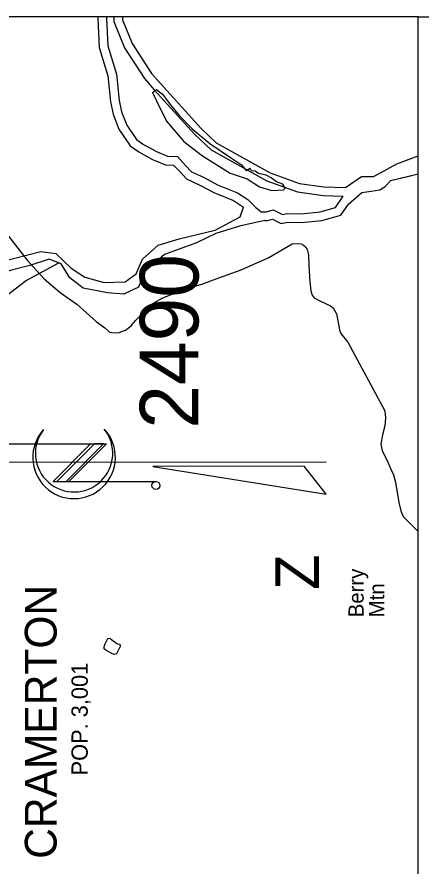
# Model space of a CAD drawing. Extents: x 1372027 to 1374286, y 553832 to 556743.
# Drawn here: x 1373419 to 1373483.1, y 554256.9 to 554391.5 of the extents above; entities that cross this region are included whole.
import ezdxf

# ---------------------------------------------------------------- set-up
doc = ezdxf.new("R2010")
doc.units = 0
for name, color, linetype in [('Old_Level_12', 7, 'Continuous'), ('Prop Dimension', 7, 'Continuous'), ('Prop Dimension Text', 7, 'Continuous'), ('Prop Lane Arrow CELL', 7, 'Continuous'), ('Prop Paved Shoulder', 7, 'Continuous'), ('Prop Terminator CELL', 7, 'Continuous'), ('Sheet Block Revision CELL', 7, 'Continuous'), ('Sheet Clip Boundary CELL', 7, 'Continuous'), ('Sheet North Arrow CELL', 7, 'Continuous'), ('Sheet Plot Border Outside CELL', 7, 'Continuous'), ('Sheet Sticker Incomplete CELL', 7, 'Continuous'), ('Sheet Sticker Preliminary CELL', 7, 'Continuous')]:
    doc.layers.add(name, color=color, linetype=linetype)

msp = doc.modelspace()

# ---------------------------------------------------------------- linework, layer by layer
at = {"layer": 'Prop Dimension'}
msp.add_lwpolyline([(1373425.61, 554352.52), (1373420.51, 554349.73), (1373415.69, 554346.11), (1373414.26, 554345.81), (1373409.04, 554343.48), (1373402.63, 554343.54), (1373401.31, 554342.34), (1373400.95, 554341.2), (1373387.17, 554323.46), (1373382.87, 554318.23)], dxfattribs=at)
at = {"layer": 'Prop Dimension Text'}
for points in [[(1373151.67, 554391.53), (1373151.67, 554060.53), (1373482.67, 554060.53), (1373482.67, 554391.53)], [(1373508.08, 554391.53), (1373508.08, 554060.53), (1373482.67, 554060.53), (1373482.67, 554391.53)]]:
    msp.add_lwpolyline(points, close=True, dxfattribs=at)
at = {"layer": 'Prop Lane Arrow CELL'}
for points in [[(1373440.5, 554379.56), (1373441.13, 554380.05), (1373442.12, 554379.28), (1373443.31, 554377.67), (1373444.79, 554375.84), (1373446.81, 554373.8), (1373449.62, 554371.48), (1373453.06, 554369.17), (1373454.61, 554368.11), (1373455.38, 554367.2), (1373456.01, 554367.55)], [(1373440.5, 554379.56), (1373441.12, 554378.23), (1373442.73, 554375), (1373445.47, 554371.77), (1373448.42, 554369.52), (1373452.85, 554366.78), (1373455.52, 554365.87), (1373457.49, 554364.6), (1373459.46, 554364.04), (1373461.28, 554364.11), (1373461.57, 554364.39), (1373461.21, 554365.02), (1373460.16, 554365.38), (1373459.32, 554366.01), (1373458.54, 554366.43), (1373457.35, 554366.71), (1373456.79, 554367.06), (1373456.22, 554367.13), (1373456.01, 554367.55)], [(1373399.91, 554348.56), (1373401.89, 554350.66), (1373405.48, 554350.79), (1373406.6, 554352.39), (1373412.17, 554351.4), (1373416.63, 554352.77), (1373422.82, 554354.37), (1373425.16, 554354.04), (1373427.61, 554351.7), (1373429.76, 554350.29), (1373432.86, 554349.42), (1373436.2, 554349.55), (1373437.94, 554350.79), (1373438.93, 554353.14), (1373441.4, 554355.37), (1373444.75, 554356.36), (1373450.45, 554357.72), (1373454.41, 554359.82), (1373454.97, 554361.36)], [(1373458.31, 554359.26), (1373454.29, 554358.34), (1373450.57, 554357.22), (1373447.47, 554355.74), (1373442.4, 554353.88), (1373439.3, 554351.16), (1373438.31, 554348.68), (1373435.95, 554347.57), (1373433.35, 554347.81), (1373429.51, 554348.56), (1373427.41, 554350.17), (1373426.04, 554352.39), (1373424.11, 554353.13), (1373421.03, 554352.12), (1373418.12, 554351.4), (1373415.27, 554350.54), (1373410.81, 554350.29), (1373406.35, 554351.03), (1373401.89, 554349.79), (1373400.28, 554348.31)]]:
    msp.add_lwpolyline(points, dxfattribs=at)
at = {"layer": 'Prop Paved Shoulder'}
msp.add_line((1373417.68, 554356.76), (1373420.64, 554352.96), dxfattribs=at)
msp.add_lwpolyline([(1373420.64, 554352.96), (1373423.32, 554350), (1373425.88, 554347.83), (1373427.28, 554346.83), (1373428.53, 554345.99), (1373431.55, 554343.24), (1373432.97, 554342.24), (1373433.65, 554341.62), (1373434.01, 554341.52), (1373434.74, 554341.46), (1373435.24, 554341.52), (1373436.22, 554341.9), (1373437.12, 554342.57), (1373437.83, 554343.42), (1373438.59, 554344.18), (1373439.86, 554345.48), (1373440.43, 554346), (1373441.19, 554346.46), (1373442.07, 554346.95), (1373443.71, 554347.63), (1373445.86, 554348.43), (1373448.49, 554349.21), (1373451.01, 554350.19), (1373454.55, 554351.43), (1373458.98, 554353.42), (1373461.13, 554354.65), (1373462.68, 554355.57), (1373463.66, 554355.63), (1373464.07, 554355.57), (1373464.45, 554355.34), (1373464.83, 554355.04), (1373465.05, 554354.65), (1373465.27, 554353.81), (1373465.33, 554352), (1373465.46, 554349.59), (1373465.65, 554348.09), (1373465.84, 554347.44), (1373466.15, 554346.98), (1373467.04, 554346.52), (1373468.77, 554345.75), (1373469.15, 554345.41), (1373469.72, 554344.47), (1373469.96, 554343.07), (1373470.2, 554341.93), (1373470.39, 554341.34), (1373471.47, 554339.98), (1373477.34, 554329.1), (1373477.47, 554327.98), (1373477.38, 554326.7), (1373476.99, 554325.3), (1373476.71, 554323.79), (1373476.93, 554322.73), (1373477.72, 554321.23), (1373478.33, 554319.82), (1373478.72, 554318.93), (1373479.06, 554317.76), (1373479.56, 554314.57), (1373479.89, 554313.23), (1373480.29, 554312.34), (1373482.67, 554309.96)], dxfattribs=at)
at = {"layer": 'Prop Terminator CELL'}
for points in [[(1373433.22, 554391.53), (1373433.2, 554391.3), (1373433.4, 554386.93), (1373434.79, 554382.48), (1373435.22, 554378.29), (1373435.6, 554376.5), (1373436.42, 554374.36), (1373437.95, 554372.1), (1373439.08, 554371.31), (1373441.12, 554370.19), (1373442.89, 554369.47), (1373444.49, 554369.39), (1373445.77, 554368), (1373446.71, 554367), (1373448.61, 554366.11), (1373450.83, 554364.94), (1373453.98, 554363.65), (1373455.62, 554362.59), (1373456.86, 554361.35), (1373457.75, 554360.64), (1373458.57, 554360.64), (1373459.67, 554360.94), (1373461.12, 554360.21), (1373461.87, 554360.36), (1373464.09, 554360.3), (1373467.11, 554360.63), (1373469.54, 554361.3), (1373470.78, 554363.12)], [(1373434.38, 554391.53), (1373434.4, 554390.8), (1373436.08, 554386.66), (1373439.23, 554381.76), (1373440.78, 554379.99), (1373447.18, 554372.94), (1373449.81, 554370.47), (1373458.63, 554365.55), (1373463.5, 554363.79), (1373467.58, 554363.21), (1373470.78, 554363.12)]]:
    msp.add_lwpolyline(points, dxfattribs=at)
at = {"layer": 'Sheet Block Revision CELL'}
msp.add_line((1373471.6, 554296.36), (1373471.6, 554296.36), dxfattribs=at)
at = {"layer": 'Sheet North Arrow CELL'}
for p, q in [((1373423.15, 554326.04), (1373423.21, 554326.12)), ((1373417.19, 554323.83), (1373433.2, 554323.84)), ((1373430.7, 554323.84), (1373424.74, 554317.87)), ((1373431.29, 554323.84), (1373425.33, 554317.87)), ((1373432.75, 554323.84), (1373426.79, 554317.87)), ((1373426.79, 554317.87), (1373432.75, 554323.84)), ((1373433.2, 554323.84), (1373427.24, 554317.87)), ((1373432.75, 554323.84), (1373431.29, 554323.84)), ((1373468.05, 554320.93), (1373390.05, 554320.86)), ((1373424.74, 554317.87), (1373441.01, 554317.88)), ((1373425.33, 554317.87), (1373426.79, 554317.87))]:
    msp.add_line(p, q, dxfattribs=at)
msp.add_lwpolyline([(1373440.57, 554320.27), (1373468.05, 554315.88), (1373464.57, 554320.29)], close=True, dxfattribs=at)
msp.add_circle((1373441.04, 554317.25), 0.636, dxfattribs=at)
for centre, radius, start, end in [((1373428.07, 554321.72), 6.55, 137.891, 42.445), ((1373428.07, 554322.36), 6.14, 143.146, 38.6797)]:
    msp.add_arc(centre, radius, start, end, dxfattribs=at)
at = {"layer": 'Sheet Plot Border Outside CELL'}
msp.add_line((1373420.61, 554352.92), (1373420.61, 554352.92), dxfattribs=at)
at = {"layer": 'Sheet Sticker Incomplete CELL'}
for points in [[(1373431.84, 554391.53), (1373431.82, 554391.33), (1373432.03, 554386.69), (1373433.44, 554382.2), (1373433.85, 554378.07), (1373434.28, 554376.11), (1373435.19, 554373.72), (1373436.95, 554371.12), (1373438.35, 554370.14), (1373440.53, 554368.94), (1373442.59, 554368.11), (1373443.85, 554368.04), (1373444.77, 554367.06), (1373445.89, 554365.86), (1373448, 554364.88), (1373450.25, 554363.69), (1373453.34, 554362.42), (1373454.97, 554361.36)], [(1373431.84, 554391.53), (1373431.82, 554391.33), (1373432.03, 554386.69), (1373433.44, 554382.2), (1373433.85, 554378.07), (1373434.28, 554376.11), (1373435.19, 554373.72), (1373436.95, 554371.12), (1373438.35, 554370.14), (1373440.53, 554368.94), (1373442.59, 554368.11), (1373443.85, 554368.04), (1373444.77, 554367.06), (1373445.89, 554365.86), (1373448, 554364.88), (1373450.25, 554363.69), (1373453.34, 554362.42), (1373454.97, 554361.36)], [(1373435.76, 554391.53), (1373435.77, 554391.09), (1373437.31, 554387.3), (1373440.33, 554382.59), (1373441.81, 554380.91), (1373448.17, 554373.91), (1373450.63, 554371.59), (1373459.2, 554366.81), (1373463.83, 554365.13), (1373467.69, 554364.58), (1373471.1, 554364.49)], [(1373435.76, 554391.53), (1373435.77, 554391.09), (1373437.31, 554387.3), (1373440.33, 554382.59), (1373441.81, 554380.91), (1373448.17, 554373.91), (1373450.63, 554371.59), (1373459.2, 554366.81), (1373463.83, 554365.13), (1373467.69, 554364.58), (1373471.1, 554364.49)], [(1373471.1, 554364.49), (1373473.66, 554366.26), (1373475.56, 554366.26), (1373476.68, 554366.83), (1373479.28, 554368.23), (1373482.67, 554369.51)], [(1373471.1, 554364.49), (1373473.66, 554366.26), (1373475.56, 554366.26), (1373476.68, 554366.83), (1373479.28, 554368.23), (1373481.65, 554369.12)], [(1373458.31, 554359.26), (1373458.75, 554359.26), (1373459.53, 554359.47), (1373460.93, 554358.77), (1373461.99, 554358.98), (1373464.14, 554358.92), (1373467.37, 554359.27), (1373470.4, 554360.11), (1373471.59, 554361.87), (1373473.7, 554363.69), (1373475.18, 554363.9), (1373476.58, 554364.11), (1373477.34, 554364.61), (1373478.28, 554365.55)], [(1373458.31, 554359.26), (1373458.75, 554359.26), (1373459.53, 554359.47), (1373460.93, 554358.77), (1373461.99, 554358.98), (1373464.14, 554358.92), (1373467.37, 554359.27), (1373470.4, 554360.11), (1373471.59, 554361.87), (1373473.7, 554363.69), (1373475.18, 554363.9), (1373476.58, 554364.11), (1373477.34, 554364.61), (1373478.28, 554365.55)], [(1373482.67, 554366.62), (1373478.28, 554365.55)], [(1373481.65, 554366.37), (1373478.28, 554365.55)]]:
    msp.add_lwpolyline(points, dxfattribs=at)
at = {"layer": 'Sheet Sticker Preliminary CELL'}
msp.add_lwpolyline([(1373433, 554292.12), (1373433.3, 554292.78), (1373433.46, 554292.99), (1373433.72, 554293.03), (1373434.01, 554292.81), (1373434.64, 554292.34), (1373434.96, 554292.16), (1373435.34, 554292.07), (1373435.38, 554291.73), (1373435.11, 554291.19), (1373434.81, 554290.57), (1373434.43, 554290.45), (1373433.97, 554290.67), (1373433.13, 554291.15), (1373432.84, 554291.37), (1373432.82, 554291.74), (1373433, 554292.12)], dxfattribs=at)

# ---------------------------------------------------------------- texts
at = {"layer": 'Old_Level_12'}
msp.add_text('2490', height=9.301, rotation=90, dxfattribs=at).set_placement((1373447.8, 554326.26))
at = {"layer": 'Sheet Block Revision CELL'}
for s, height, p in [('Z', 6.89, (1373466.9, 554300.68)), ('Berry', 2.411, (1373474.01, 554296.36)), ('Mtn', 2.411, (1373477.28, 554296.36))]:
    msp.add_text(s, height=height, rotation=90, dxfattribs=at).set_placement(p)
at = {"layer": 'Sheet Clip Boundary CELL'}
for s, height, p in [('CRAMERTON', 5.04, (1373425.3, 554258.06)), ('POP. 3,001', 2.584, (1373430.24, 554271.28))]:
    msp.add_text(s, height=height, rotation=90, dxfattribs=at).set_placement(p)

doc.saveas('drawing.dxf')
